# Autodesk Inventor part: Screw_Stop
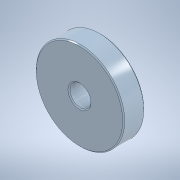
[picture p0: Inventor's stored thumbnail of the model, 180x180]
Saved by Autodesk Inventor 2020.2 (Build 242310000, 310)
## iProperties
Created: 2020-01
Part Number: Screw_Stop
Material: Steel
Document SubType Name: Modeling
Designer: Patrick Everitt
Density: 7.85 g/cm^3
Appearance: Steel Blue
Author: Patrick Everitt
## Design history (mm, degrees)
sketch "Sketch1"
  geometry: C1 r 3.969 at (0, 0); C2 r 16.669 at (0, 0); 1 further point
  constraints: 2 centre point, 2 coincident
  dimensions: "d0" = 7.9375 diameter of C1; "d1" = 33.3375 diameter of C2
extrude "Extrusion1" new body sketch "Sketch1" distance "d2" = 7.9375; taper "d3" = 0 deg
chamfer "Chamfer1" distance "d4" = 0.381; stored, may be unused: second distance "d5" = 3.175, angle "d6" = 45 deg
chamfer "Chamfer2" distance "d7" = 0.381; stored, may be unused: second distance "d8" = 3.175, angle "d9" = 45 deg
chamfer "Chamfer3" distance "d10" = 0.381; stored, may be unused: second distance "d11" = 3.175, angle "d12" = 45 deg
chamfer "Chamfer4" distance "d13" = 0.381; stored, may be unused: second distance "d14" = 3.175, angle "d15" = 45 deg
body "Solid1"
